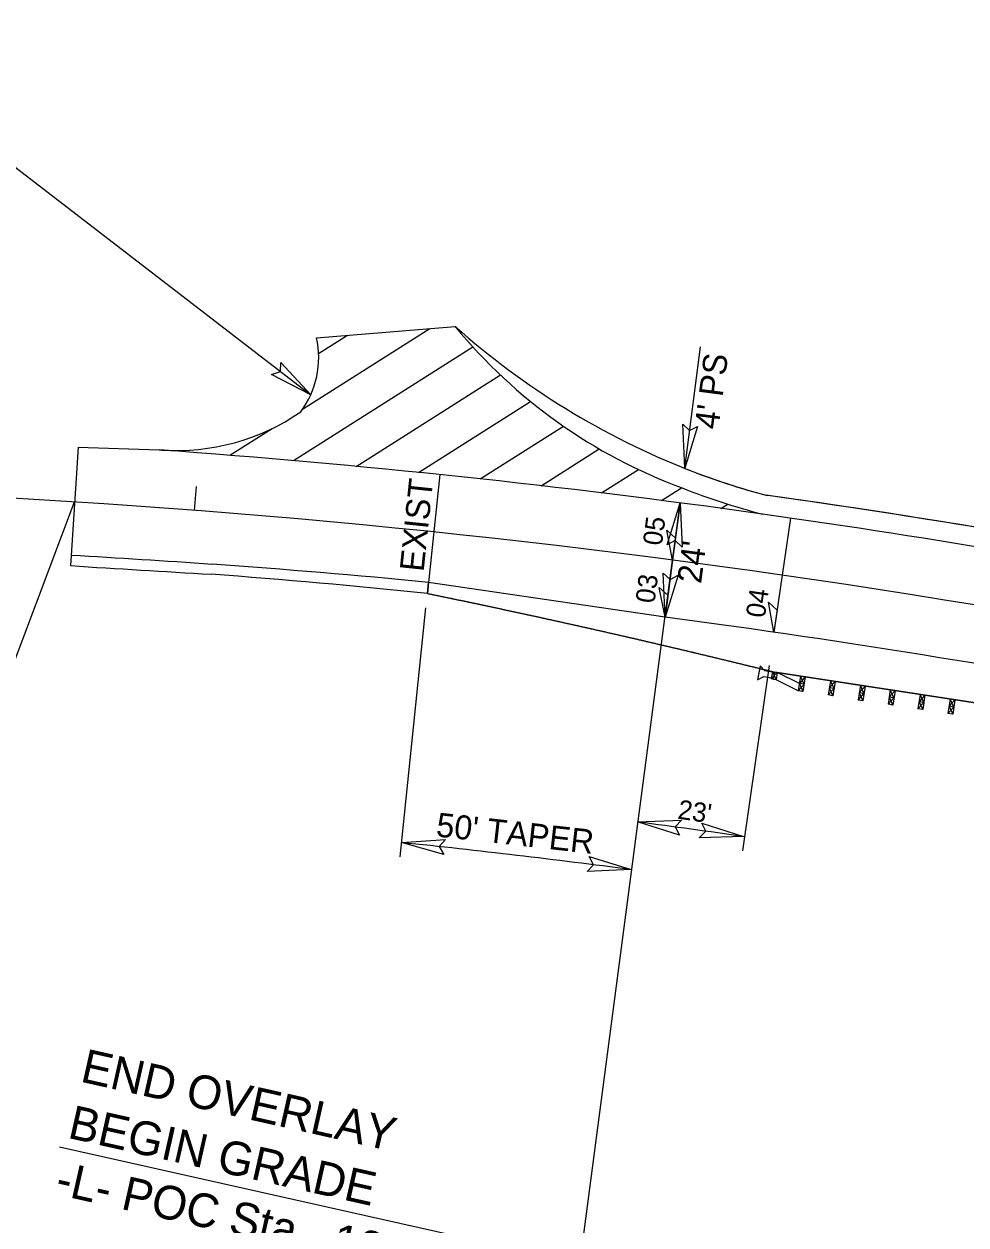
# Model space of a CAD drawing. Extents: x 1784740 to 1786163, y 841056 to 841833.
# Drawn here: x 1785030.5 to 1785226.5, y 841407.2 to 841657.2 of the extents above; entities that cross this region are included whole.
import ezdxf

# ---------------------------------------------------------------- set-up
doc = ezdxf.new("R2010")
doc.units = 0
for name, color, linetype in [('Old_Level_3', 7, 'Continuous'), ('Prop Dimension', 7, 'Continuous'), ('Prop EOT', 7, 'Continuous'), ('Prop Guardrail Anchor Unit CELL', 7, 'Continuous'), ('Prop Horizontal Alignment', 7, 'Continuous'), ('Prop Horizontal Alignment Station Label', 7, 'Continuous'), ('Prop Horizontal Alignment Tick Small', 7, 'Continuous'), ('Prop Paved Shoulder', 7, 'Continuous'), ('Prop Shade Light', 7, 'Continuous'), ('Prop Shade Medium', 7, 'Continuous'), ('Prop Superelevation  Arrow CELL', 7, 'Continuous'), ('Prop Superelevation Label', 7, 'Continuous'), ('Prop Terminator CELL', 7, 'Continuous')]:
    doc.layers.add(name, color=color, linetype=linetype)

msp = doc.modelspace()

# ---------------------------------------------------------------- linework, layer by layer
at = {"layer": 'Old_Level_3'}
msp.add_line((1785117.04, 841563.38), (1785114.7, 841540.93), dxfattribs=at)
at = {"layer": 'Prop Dimension'}
for p, q in [((1784989.97, 841657.17), (1785090.18, 841580)), ((1785167.97, 841564.71), (1785171.28, 841589.95)), ((1785163.89, 841533.71), (1785167.02, 841557.5)), ((1785108.76, 841483.81), (1785114.16, 841535.67))]:
    msp.add_line(p, q, dxfattribs=at)
msp.add_arc((1784924.4, 839711.38), 1785, 82.51319, 84.06172, dxfattribs=at)
at = {"layer": 'Prop EOT'}
for p, q in [((1785091.38, 841591.87), (1785120.25, 841594.2)), ((1785041.79, 841569.12), (1785040.36, 841546.57)), ((1785041.79, 841569.12), (1785058.67, 841568.53)), ((1785163.89, 841533.71), (1785114.7, 841540.93))]:
    msp.add_line(p, q, dxfattribs=at)
for centre, radius, start, end in [((1785205.84, 841664.53), 110.78, 219.4093, 249.7132), ((1784924.4, 839711.38), 1862, 81.98136, 85.86495), ((1785221.44, 841697.97), 147.59, 248.5329, 255.3621), ((1784924.4, 839711.38), 1862, 75.31501, 81.98136), ((1784924.4, 839711.38), 1838, 75.31501, 82.51319)]:
    msp.add_arc(centre, radius, start, end, dxfattribs=at)
for centre, major_axis, ratio, start_param, end_param in [((1785072.9, 841587.72), (8.59, 16.9), 0.998809, 4.544918, 5.402332), ((1785062.28, 841613.9), (38.46, 24.32), 0.999812, 4.080453, 4.752096), ((1785111.18, 843301.81), (613.02, -1622.11), 0.999956, 5.89156, 5.891859), ((1784845.01, 838284.83), (-3298.97, 29.38), 0.990423, 4.653056, 4.661961), ((1784975.54, 840160.03), (-1388.41, -42.4), 0.999146, 4.581528, 4.614058)]:
    msp.add_ellipse(centre, major_axis=major_axis, ratio=ratio, start_param=start_param, end_param=end_param, dxfattribs=at)
at = {"layer": 'Prop Guardrail Anchor Unit CELL'}
for p, q in [((1785183.64, 841523.59), (1785183.14, 841520.7)), ((1785184.65, 841522.54), (1785183.64, 841523.59)), ((1785183.14, 841520.7), (1785184.44, 841521.34)), ((1785184.44, 841521.34), (1785186.46, 841520.99)), ((1785186.67, 841522.2), (1785184.65, 841522.54)), ((1785186.22, 841522.34), (1785185.99, 841520.86)), ((1785185.99, 841520.86), (1785187.2, 841522.19)), ((1785186.98, 841520.71), (1785185.99, 841520.86)), ((1785186.22, 841522.34), (1785186.98, 841520.71)), ((1785186.46, 841520.99), (1785186.56, 841521.6)), ((1785186.98, 841520.71), (1785186.48, 841520.78)), ((1785186.56, 841521.6), (1785186.67, 841522.2)), ((1785232.92, 841515.18), (1785186.71, 841522.27)), ((1785187.2, 841522.19), (1785186.98, 841520.71)), ((1785191.58, 841518.42), (1785186.98, 841520.71)), ((1785191.82, 841519.93), (1785187.2, 841522.19)), ((1785192.05, 841521.45), (1785191.58, 841518.42)), ((1785193.04, 841521.3), (1785191.82, 841519.93)), ((1785192.81, 841519.78), (1785192.05, 841521.45)), ((1785193.04, 841521.3), (1785192.57, 841518.27)), ((1785198.28, 841520.49), (1785197.82, 841517.53)), ((1785199.27, 841520.34), (1785198.05, 841519.01)), ((1785199.04, 841518.86), (1785198.28, 841520.49)), ((1785199.27, 841520.34), (1785198.81, 841517.38)), ((1785191.58, 841518.42), (1785192.81, 841519.78)), ((1785192.57, 841518.27), (1785191.58, 841518.42)), ((1785192.81, 841519.78), (1785191.82, 841519.93)), ((1785191.82, 841519.93), (1785192.57, 841518.27)), ((1785197.82, 841517.53), (1785199.04, 841518.86)), ((1785199.04, 841518.86), (1785198.05, 841519.01)), ((1785198.05, 841519.01), (1785198.81, 841517.38)), ((1785204.51, 841519.54), (1785204.03, 841516.44)), ((1785205.49, 841519.39), (1785204.27, 841517.99)), ((1785205.26, 841517.84), (1785204.27, 841517.99)), ((1785204.27, 841517.99), (1785205.02, 841516.29)), ((1785205.26, 841517.84), (1785204.51, 841519.54)), ((1785205.49, 841519.39), (1785205.02, 841516.29)), ((1785210.73, 841518.58), (1785210.27, 841515.58)), ((1785211.72, 841518.43), (1785210.5, 841517.08)), ((1785211.72, 841518.43), (1785210.73, 841518.58)), ((1785211.49, 841516.93), (1785210.73, 841518.58)), ((1785211.72, 841518.43), (1785211.26, 841515.43)), ((1785198.81, 841517.38), (1785197.82, 841517.53)), ((1785204.03, 841516.44), (1785205.26, 841517.84)), ((1785205.02, 841516.29), (1785204.03, 841516.44)), ((1785210.27, 841515.58), (1785211.49, 841516.93)), ((1785211.26, 841515.43), (1785210.27, 841515.58)), ((1785211.49, 841516.93), (1785210.5, 841517.08)), ((1785210.5, 841517.08), (1785211.26, 841515.43)), ((1785216.96, 841517.63), (1785216.5, 841514.62)), ((1785216.5, 841514.62), (1785217.72, 841515.97)), ((1785217.95, 841517.48), (1785216.73, 841516.12)), ((1785217.72, 841515.97), (1785216.73, 841516.12)), ((1785216.73, 841516.12), (1785217.49, 841514.47)), ((1785217.72, 841515.97), (1785216.96, 841517.63)), ((1785217.95, 841517.48), (1785217.49, 841514.47)), ((1785223.19, 841516.67), (1785222.73, 841513.66)), ((1785224.18, 841516.52), (1785222.96, 841515.17)), ((1785223.95, 841515.01), (1785223.19, 841516.67)), ((1785224.18, 841516.52), (1785223.72, 841513.51)), ((1785217.49, 841514.47), (1785216.5, 841514.62)), ((1785222.73, 841513.66), (1785223.95, 841515.01)), ((1785223.72, 841513.51), (1785222.73, 841513.66)), ((1785223.95, 841515.01), (1785222.96, 841515.17)), ((1785222.96, 841515.17), (1785223.72, 841513.51))]:
    msp.add_line(p, q, dxfattribs=at)
at = {"layer": 'Prop Horizontal Alignment'}
msp.add_arc((1784924.4, 839711.38), 1850, 75.31501, 88.70732, dxfattribs=at)
at = {"layer": 'Prop Horizontal Alignment Station Label'}
for p, q in [((1784959.55, 841341.9), (1785041.06, 841557.69)), ((1785146.21, 841399.16), (1785165.45, 841545.61)), ((1785146.21, 841399.16), (1785037.96, 841423.43))]:
    msp.add_line(p, q, dxfattribs=at)
at = {"layer": 'Prop Horizontal Alignment Tick Small'}
for p, q in [((1785066, 841555.95), (1785066.39, 841560.93)), ((1785165.45, 841545.61), (1785166.11, 841550.56))]:
    msp.add_line(p, q, dxfattribs=at)
at = {"layer": 'Prop Paved Shoulder'}
for p, q in [((1785040.36, 841546.57), (1785040.23, 841544.44)), ((1785114.7, 841540.93), (1785114.47, 841538.65)), ((1785232.92, 841515.18), (1785186.71, 841522.27))]:
    msp.add_line(p, q, dxfattribs=at)
for centre, radius, start, end in [((1785228.61, 841716.2), 163.18, 228.3886, 248.5329), ((1785205.84, 841664.53), 106.78, 249.2251, 249.7132), ((1785221.44, 841697.97), 143.59, 248.5329, 255.3621), ((1784924.4, 839711.38), 1866, 78.35834, 81.98136)]:
    msp.add_arc(centre, radius, start, end, dxfattribs=at)
for centre, major_axis, ratio, start_param, end_param in [((1785273.77, 845367.26), (4154.31, -331.76), 0.918971, 4.729551, 4.736578), ((1784957.98, 840038.14), (-1503.92, -126.32), 0.999609, 4.524746, 4.554691)]:
    msp.add_ellipse(centre, major_axis=major_axis, ratio=ratio, start_param=start_param, end_param=end_param, dxfattribs=at)
msp.add_spline([(1785114.47, 841538.65), (1785115.45, 841538.45), (1785116.43, 841538.25), (1785117.41, 841538.04), (1785118.4, 841537.84), (1785119.38, 841537.64), (1785120.36, 841537.43), (1785121.34, 841537.23), (1785122.32, 841537.02), (1785123.3, 841536.81), (1785124.28, 841536.61), (1785125.27, 841536.4), (1785126.25, 841536.19), (1785127.23, 841535.98), (1785128.21, 841535.77), (1785129.19, 841535.56), (1785130.17, 841535.35), (1785131.15, 841535.14), (1785132.13, 841534.93), (1785133.11, 841534.72), (1785134.09, 841534.51), (1785135.06, 841534.29), (1785136.04, 841534.08), (1785137.02, 841533.87), (1785138, 841533.65), (1785138.98, 841533.44), (1785139.96, 841533.22), (1785140.94, 841533.01), (1785141.91, 841532.79), (1785142.89, 841532.57), (1785143.87, 841532.36), (1785144.85, 841532.14), (1785145.82, 841531.92), (1785146.8, 841531.7), (1785147.78, 841531.48), (1785148.75, 841531.26), (1785149.73, 841531.04), (1785150.71, 841530.82), (1785151.68, 841530.6), (1785152.66, 841530.37), (1785153.64, 841530.15), (1785154.61, 841529.93), (1785155.59, 841529.71), (1785156.56, 841529.48), (1785157.54, 841529.26), (1785158.51, 841529.03), (1785159.49, 841528.8), (1785160.46, 841528.58), (1785161.44, 841528.35), (1785162.41, 841528.12), (1785163.38, 841527.9), (1785164.36, 841527.67), (1785165.33, 841527.44), (1785166.31, 841527.21), (1785167.28, 841526.98), (1785168.25, 841526.75), (1785169.22, 841526.52), (1785170.2, 841526.29), (1785171.17, 841526.05), (1785172.14, 841525.82), (1785173.11, 841525.59), (1785174.09, 841525.35), (1785175.06, 841525.12), (1785176.03, 841524.88), (1785177, 841524.65), (1785177.97, 841524.41), (1785178.95, 841524.18), (1785179.92, 841523.94), (1785180.89, 841523.7), (1785181.86, 841523.47), (1785182.83, 841523.23), (1785183.8, 841522.99), (1785184.77, 841522.75), (1785186.71, 841522.27)], degree=3, dxfattribs=at)
at = {"layer": 'Prop Shade Light'}
for p, q in [((1785114.7, 841540.93), (1785114.47, 841538.65)), ((1785163.89, 841533.71), (1785114.7, 841540.93)), ((1785186.71, 841522.27), (1785232.92, 841515.18))]:
    msp.add_line(p, q, dxfattribs=at)
for centre, radius, start, end in [((1785228.61, 841716.2), 163.18, 228.3886, 248.5329), ((1785205.84, 841664.53), 110.78, 219.4093, 249.7132), ((1785221.44, 841697.97), 143.59, 248.5329, 255.2705), ((1785221.44, 841697.97), 147.59, 248.5329, 255.3621), ((1784924.4, 839711.38), 1866, 78.35834, 81.97421), ((1784924.4, 839711.38), 1862, 75.31501, 81.98136), ((1784924.4, 839711.38), 1838, 75.31501, 82.51319)]:
    msp.add_arc(centre, radius, start, end, dxfattribs=at)
for points in [[(1785114.47, 841538.65), (1785114.8, 841538.59), (1785115.12, 841538.52), (1785115.45, 841538.45), (1785115.78, 841538.38), (1785116.11, 841538.32), (1785116.43, 841538.25), (1785116.76, 841538.18), (1785117.09, 841538.11), (1785117.41, 841538.04), (1785117.74, 841537.98), (1785118.07, 841537.91), (1785118.4, 841537.84), (1785118.72, 841537.77), (1785119.05, 841537.7), (1785119.38, 841537.64), (1785119.71, 841537.57), (1785120.03, 841537.5), (1785120.36, 841537.43), (1785120.69, 841537.36), (1785121.01, 841537.29), (1785121.34, 841537.23), (1785121.67, 841537.16), (1785122, 841537.09), (1785122.32, 841537.02), (1785122.65, 841536.95), (1785122.98, 841536.88), (1785123.3, 841536.81), (1785123.63, 841536.74), (1785123.96, 841536.68), (1785124.28, 841536.61), (1785124.61, 841536.54), (1785124.94, 841536.47), (1785125.27, 841536.4), (1785125.59, 841536.33), (1785125.92, 841536.26), (1785126.25, 841536.19), (1785126.57, 841536.12), (1785126.9, 841536.05), (1785127.23, 841535.98), (1785127.55, 841535.91), (1785127.88, 841535.84), (1785128.21, 841535.77), (1785128.53, 841535.7), (1785128.86, 841535.63), (1785129.19, 841535.56), (1785129.51, 841535.49), (1785129.84, 841535.42), (1785130.17, 841535.35), (1785130.49, 841535.28), (1785130.82, 841535.21), (1785131.15, 841535.14), (1785131.47, 841535.07), (1785131.8, 841535), (1785132.13, 841534.93), (1785132.45, 841534.86), (1785132.78, 841534.79), (1785133.11, 841534.72), (1785133.43, 841534.65), (1785133.76, 841534.58), (1785134.09, 841534.51), (1785134.41, 841534.44), (1785134.74, 841534.37), (1785135.06, 841534.29), (1785135.39, 841534.22), (1785135.72, 841534.15), (1785136.04, 841534.08), (1785136.37, 841534.01), (1785136.7, 841533.94), (1785137.02, 841533.87), (1785137.35, 841533.8), (1785137.67, 841533.72), (1785138, 841533.65), (1785138.21, 841533.61), (1785138.41, 841533.56), (1785138.62, 841533.52)], [(1785138.62, 841533.52), (1785138.74, 841533.49), (1785138.86, 841533.46), (1785138.98, 841533.44), (1785139.31, 841533.37), (1785139.63, 841533.29), (1785139.96, 841533.22), (1785140.28, 841533.15), (1785140.61, 841533.08), (1785140.94, 841533.01), (1785141.26, 841532.94), (1785141.59, 841532.86), (1785141.91, 841532.79), (1785142.24, 841532.72), (1785142.57, 841532.65), (1785142.89, 841532.57), (1785143.22, 841532.5), (1785143.54, 841532.43), (1785143.87, 841532.36), (1785144.19, 841532.28), (1785144.52, 841532.21), (1785144.85, 841532.14), (1785145.17, 841532.07), (1785145.5, 841531.99), (1785145.82, 841531.92), (1785146.15, 841531.85), (1785146.47, 841531.77), (1785146.8, 841531.7), (1785147.13, 841531.63), (1785147.45, 841531.55), (1785147.78, 841531.48), (1785148.1, 841531.41), (1785148.43, 841531.33), (1785148.75, 841531.26), (1785149.08, 841531.19), (1785149.41, 841531.11), (1785149.73, 841531.04), (1785150.06, 841530.97), (1785150.38, 841530.89), (1785150.71, 841530.82), (1785151.03, 841530.75), (1785151.36, 841530.67), (1785151.68, 841530.6), (1785152.01, 841530.52), (1785152.33, 841530.45), (1785152.66, 841530.37), (1785152.98, 841530.3), (1785153.31, 841530.23), (1785153.64, 841530.15), (1785153.96, 841530.08), (1785154.29, 841530), (1785154.61, 841529.93), (1785154.94, 841529.85), (1785155.26, 841529.78), (1785155.59, 841529.71), (1785155.91, 841529.63), (1785156.24, 841529.56), (1785156.56, 841529.48), (1785156.89, 841529.41), (1785157.21, 841529.33), (1785157.54, 841529.26), (1785157.86, 841529.18), (1785158.19, 841529.11), (1785158.51, 841529.03), (1785158.84, 841528.96), (1785159.16, 841528.88), (1785159.49, 841528.8), (1785159.81, 841528.73), (1785160.14, 841528.65), (1785160.46, 841528.58), (1785160.79, 841528.5), (1785161.11, 841528.43), (1785161.44, 841528.35), (1785161.76, 841528.28), (1785162.09, 841528.2), (1785162.41, 841528.12), (1785162.51, 841528.1), (1785162.61, 841528.08), (1785162.7, 841528.06)], [(1785162.7, 841528.06), (1785162.93, 841528), (1785163.16, 841527.95), (1785163.38, 841527.9), (1785163.71, 841527.82), (1785164.03, 841527.74), (1785164.36, 841527.67), (1785164.68, 841527.59), (1785165.01, 841527.51), (1785165.33, 841527.44), (1785165.66, 841527.36), (1785165.98, 841527.29), (1785166.31, 841527.21), (1785166.63, 841527.13), (1785166.95, 841527.06), (1785167.28, 841526.98), (1785167.6, 841526.9), (1785167.93, 841526.83), (1785168.25, 841526.75), (1785168.58, 841526.67), (1785168.9, 841526.59), (1785169.22, 841526.52), (1785169.55, 841526.44), (1785169.87, 841526.36), (1785170.2, 841526.29), (1785170.52, 841526.21), (1785170.85, 841526.13), (1785171.17, 841526.05), (1785171.49, 841525.98), (1785171.82, 841525.9), (1785172.14, 841525.82), (1785172.47, 841525.74), (1785172.79, 841525.67), (1785173.11, 841525.59), (1785173.44, 841525.51), (1785173.76, 841525.43), (1785174.09, 841525.35), (1785174.41, 841525.28), (1785174.74, 841525.2), (1785175.06, 841525.12), (1785175.38, 841525.04), (1785175.71, 841524.96), (1785176.03, 841524.88), (1785176.35, 841524.81), (1785176.68, 841524.73), (1785177, 841524.65), (1785177.33, 841524.57), (1785177.65, 841524.49), (1785177.97, 841524.41), (1785178.3, 841524.33), (1785178.62, 841524.26), (1785178.95, 841524.18), (1785179.27, 841524.1), (1785179.59, 841524.02), (1785179.92, 841523.94), (1785180.24, 841523.86), (1785180.56, 841523.78), (1785180.89, 841523.7), (1785181.21, 841523.62), (1785181.53, 841523.54), (1785181.86, 841523.47), (1785182.18, 841523.39), (1785182.5, 841523.31), (1785182.83, 841523.23), (1785183.15, 841523.15), (1785183.47, 841523.07), (1785183.8, 841522.99), (1785184.12, 841522.91), (1785184.45, 841522.83), (1785184.77, 841522.75), (1785185.42, 841522.59), (1785186.06, 841522.43), (1785186.71, 841522.27)]]:
    msp.add_open_spline(points, degree=3, dxfattribs=at)
at = {"layer": 'Prop Shade Medium'}
for p, q in [((1785088.49, 841576.99), (1785114.97, 841593.77)), ((1785091.81, 841588.57), (1785097.84, 841592.39)), ((1785086.57, 841566.3), (1785123.91, 841589.96)), ((1785099.64, 841565.11), (1785129.63, 841584.12)), ((1785112.58, 841563.84), (1785135.9, 841578.62)), ((1785073.37, 841567.41), (1785082.19, 841573)), ((1785125.4, 841562.5), (1785142.73, 841573.48)), ((1785138.1, 841561.07), (1785150.19, 841568.74)), ((1785150.69, 841559.58), (1785158.36, 841564.44)), ((1785163.16, 841558.01), (1785167.33, 841560.65)), ((1785175.51, 841556.37), (1785176.92, 841557.26)), ((1785040.36, 841546.57), (1785040.23, 841544.44)), ((1785114.47, 841538.65), (1785114.7, 841540.93))]:
    msp.add_line(p, q, dxfattribs=at)
for centre, major_axis, ratio, start_param, end_param in [((1784845.01, 838284.83), (-3298.97, 29.38), 0.990423, 4.653056, 4.661961), ((1785273.77, 845367.26), (4154.31, -331.76), 0.918971, 4.729551, 4.736578), ((1784975.54, 840160.03), (-1388.41, -42.4), 0.999146, 4.581528, 4.614058), ((1784957.98, 840038.14), (-1503.92, -126.32), 0.999609, 4.524746, 4.554691)]:
    msp.add_ellipse(centre, major_axis=major_axis, ratio=ratio, start_param=start_param, end_param=end_param, dxfattribs=at)
at = {"layer": 'Prop Superelevation  Arrow CELL'}
for points in [[(1785165.45, 841545.61), (1785164.25, 841551.81), (1785166.06, 841550.19)], [(1785163.89, 841533.71), (1785162.69, 841539.92), (1785164.49, 841538.29)], [(1785186.53, 841530.59), (1785185.4, 841536.81), (1785187.19, 841535.17)]]:
    msp.add_lwpolyline(points, close=True, dxfattribs=at)
at = {"layer": 'Prop Superelevation Label'}
for p, q in [((1785167.02, 841557.5), (1785165.45, 841545.61)), ((1785189.95, 841554.34), (1785186.53, 841530.59)), ((1785165.45, 841545.61), (1785163.89, 841533.71)), ((1785185.53, 841523.66), (1785179.97, 841485.06))]:
    msp.add_line(p, q, dxfattribs=at)
msp.add_arc((1784924.4, 839711.38), 1795, 81.80086, 82.51319, dxfattribs=at)
at = {"layer": 'Prop Terminator CELL'}
for points in [[(1785083.99, 841586.71), (1785090.18, 841580), (1785082.03, 841584.25), (1785083.92, 841584.82)], [(1785170.67, 841573.43), (1785167.97, 841564.71), (1785167.56, 841573.89), (1785168.99, 841572.54)], [(1785164.31, 841548.78), (1785167.02, 841557.5), (1785167.43, 841548.32), (1785165.99, 841549.67)], [(1785166.6, 841542.43), (1785163.89, 841533.71), (1785163.48, 841542.89), (1785164.92, 841541.54)], [(1785166.88, 841488.38), (1785158.15, 841491.09), (1785167.34, 841491.5), (1785165.99, 841490.06)], [(1785171.51, 841490.87), (1785180.2, 841488.05), (1785171.01, 841487.76), (1785172.38, 841489.18)], [(1785117.87, 841484.33), (1785109.07, 841486.8), (1785118.24, 841487.45), (1785116.93, 841485.98)], [(1785148.13, 841483.88), (1785156.85, 841481.18), (1785147.67, 841480.77), (1785149.02, 841482.2)]]:
    msp.add_lwpolyline(points, close=True, dxfattribs=at)

# ---------------------------------------------------------------- texts
at = {"layer": 'Prop Dimension'}
for s, rotation, p in [("4' PS", 82.5132, (1785174.96, 841572.64)), ('EXIST', 84.0617, (1785113.66, 841543.05)), ("24'", 82.5132, (1785171.37, 841540.56)), ("50' TAPER", 353.6182, (1785116.12, 841488.1))]:
    msp.add_text(s, height=5, rotation=rotation, dxfattribs=at).set_placement(p)
at = {"layer": 'Prop Horizontal Alignment Station Label'}
for s, p in [('END OVERLAY', (1785042.03, 841437.1)), ('BEGIN GRADE', (1785039.41, 841425.39)), ('-L- POC Sta.  12+00.00', (1785036.78, 841413.68))]:
    msp.add_text(s, height=7, rotation=347.3599, dxfattribs=at).set_placement(p)
at = {"layer": 'Prop Superelevation Label'}
for s, rotation, p in [('05', 82.5132, (1785163.21, 841548.48)), ('03', 82.5132, (1785161.68, 841536.48)), ('04', 81.8009, (1785184.63, 841533.44)), ("23'", 352.1361, (1785166.37, 841491.79))]:
    msp.add_text(s, height=4, rotation=rotation, dxfattribs=at).set_placement(p)

doc.saveas('drawing.dxf')
